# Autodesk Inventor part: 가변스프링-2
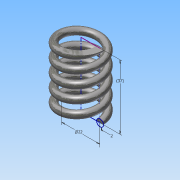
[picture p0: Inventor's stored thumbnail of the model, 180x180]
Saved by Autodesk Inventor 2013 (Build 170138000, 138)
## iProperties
Created: 2016-01
Part Number: 가변스프링-2
Material: 스테인리스강
Document SubType Name: Modeling
Designer: Administrator
Mass: 33.9044 g
Surface Area: 43.1153 cm^2
Volume: 4.19609 cm^3
Density: 8.08 g/cm^3
Author: Administrator
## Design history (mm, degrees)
sketch "스케치1"
  geometry: L1 (0, 0)-(11, 0); L2 (11, 0)-(11, 25.358); L3 (11, 25.358)-(0, 25.358); L4 (0, 25.358)-(0, 0); C1 r 2 at (11, 0)
  constraints: 8 end point, 2 parallel, 1 centre point, 1 coincident, 1 horizontal, 1 perpendicular
  dimensions: "d0" = 2 radius of C1; "d1" = 22 diameter of L2 L4; "d2" = 25.35829 distance between parallel lines of L3 L1 (derived)
feature "코일1" sketch "스케치1" pitch "d3" = 10; turns "d5" = 5; dims "d4" = 25.35829 (= d2), "d6" = 0, angle "d7" = 90 deg, angle "d8" = 90 deg, "d9" = 0, "d10" = 0
feature "분할1"
node "작업 평면1"
feature "분할2"
node "솔리드1"
other parameters: "d11" = 90 deg
